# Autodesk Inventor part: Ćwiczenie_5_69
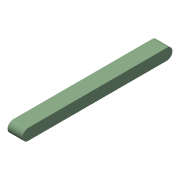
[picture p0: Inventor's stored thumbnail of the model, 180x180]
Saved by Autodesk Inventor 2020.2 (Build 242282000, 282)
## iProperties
Created: 2005-07
Part Number: Ćwiczenie_5_69
Document SubType Name: Modeling
Designer: F.Stasiak
Manufacturer: Standard
Standards Organization: Custom
Density: 1 g/cm^3
Material: Ogólny
Appearance: Zielony pastelowy
Manager: www.cadconsulting.pl
Company: Fabian Stasiak CAD Consulting
Author: F.Stasiak
Subject: Zbiór ćwiczeń. Autodesk Inventor 2020. Kurs podstawowy
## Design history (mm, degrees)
sketch "Szkic1"
  geometry: L1 (0, 0)-(80, 0); L2 (80, 0)-(80, 8); L3 (80, 8)-(0, 8); L4 (0, 8)-(0, 0)
  constraints: 8 end point, 2 parallel, 1 horizontal, 1 perpendicular
  dimensions: "d0" = 80 distance of L1.start L1.end; "d1" = 8 distance of L3.end L1.start
extrude "Wyciągnięcie proste1" new body sketch "Szkic1" distance "d2" = 6; taper "d3" = 0 deg
fillet "Zaokrąglenie1" dims "d4" = 3
node "Bryła1"
node "Korpusy bryłowe"
node "Korpusy powierzchniowe"
